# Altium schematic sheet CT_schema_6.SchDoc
size 254 x 194 mm
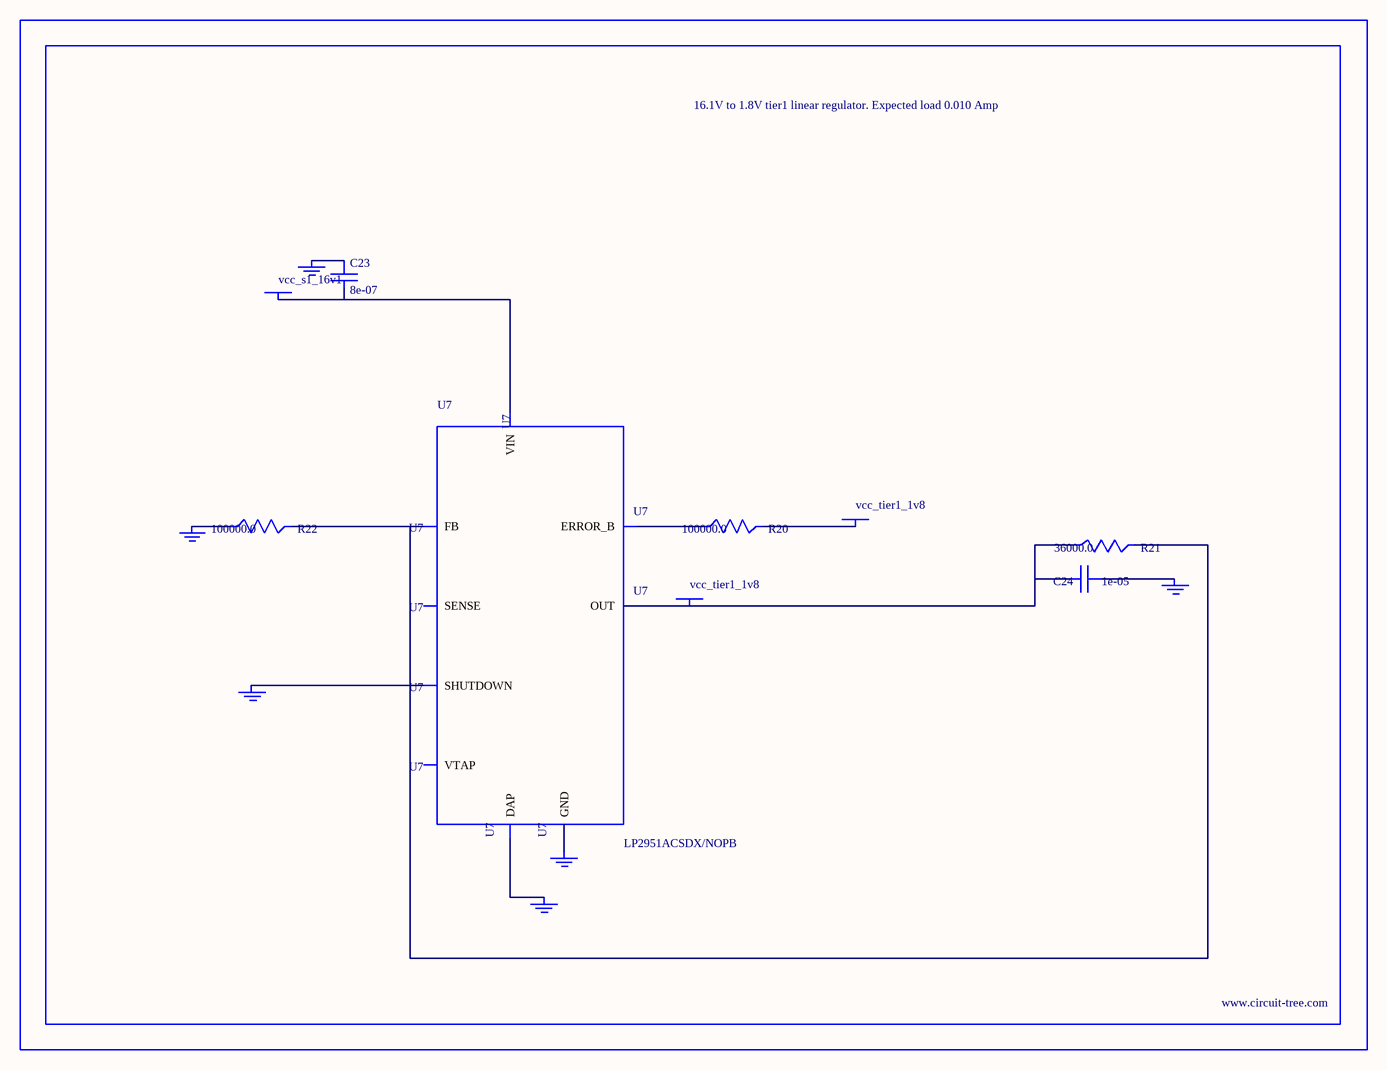
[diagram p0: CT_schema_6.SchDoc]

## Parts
BORDER5  (no value)
C23  8e-07  [R0603]
C24  1e-05  [C0805]
GND_INSTANCE_5_0  (no value)
GND_INSTANCE_5_1  (no value)
GND_INSTANCE_5_2  (no value)
GND_INSTANCE_5_3  (no value)
GND_INSTANCE_5_4  (no value)
GND_INSTANCE_5_5  (no value)
POWER_INSTANCE_5_0  vcc_tier1_1v8
POWER_INSTANCE_5_1  vcc_s1_16v1
POWER_INSTANCE_5_2  vcc_tier1_1v8
R20  100000.0  [R0603]
R21  36000.0  [R0603]
R22  100000.0  [R0603]
U7  LP2951ACSDX/NOPB  [WSON-8]

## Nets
NetC23_1: C23.1 GND_INSTANCE_5_3.0(GND)
NetC23_2: C23.2 POWER_INSTANCE_5_1.0(PWR) U7.8(VIN)
NetC24_1: C24.1 GND_INSTANCE_5_0.0(GND)
NetC24_2: C24.2 POWER_INSTANCE_5_2.0(PWR) R21.1 U7.1(OUT)
NetGND_INSTANCE_5_1_0: GND_INSTANCE_5_1.0(GND) U7.3(SHUTDOWN)
NetGND_INSTANCE_5_2_0: GND_INSTANCE_5_2.0(GND) R22.1
NetGND_INSTANCE_5_4_0: GND_INSTANCE_5_4.0(GND) U7.PAD(DAP)
NetGND_INSTANCE_5_5_0: GND_INSTANCE_5_5.0(GND) U7.4(GND)
NetPOWER_INSTANCE_5_0_0: POWER_INSTANCE_5_0.0(PWR) R20.2
NetR20_1: R20.1 U7.5(ERROR_B)
NetR21_2: R21.2 R22.2 U7.7(FB)

Not connected (* = marked no-connect by the designer): U7 2(SENSE) 6(VTAP)

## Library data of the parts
BORDER5 = BORDER_PAGE5
C23 = C23
C24 = GRM219R60J106ME19D
GND_INSTANCE_5_0-GND_INSTANCE_5_5 = GND
POWER_INSTANCE_5_0-POWER_INSTANCE_5_2 = PWR
R20 R22 = RC0603JR-07100KL
R21 = RC0603JR-0736KL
